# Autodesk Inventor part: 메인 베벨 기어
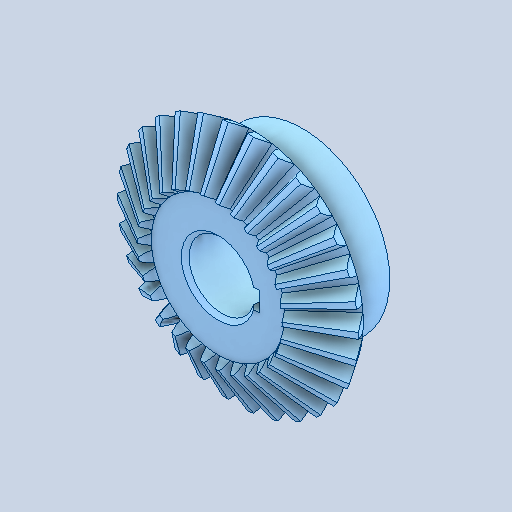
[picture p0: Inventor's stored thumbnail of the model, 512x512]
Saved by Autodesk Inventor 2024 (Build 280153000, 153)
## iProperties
Created: 2026-07
Part Number: 메인 베벨 기어
Material: 강철, 합금
Document SubType Name: Modeling
Designer: com
Density: 7.73 g/cm^3
Appearance: 기본값
Author: jhkim
Revision Number: 1
Sending System: Autodesk Inventor 2027
Preprocessor: ST-DEVELOPER v20.1
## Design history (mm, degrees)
node "메인 베벨기어1"
node "솔리드1"
body "Solid1"
